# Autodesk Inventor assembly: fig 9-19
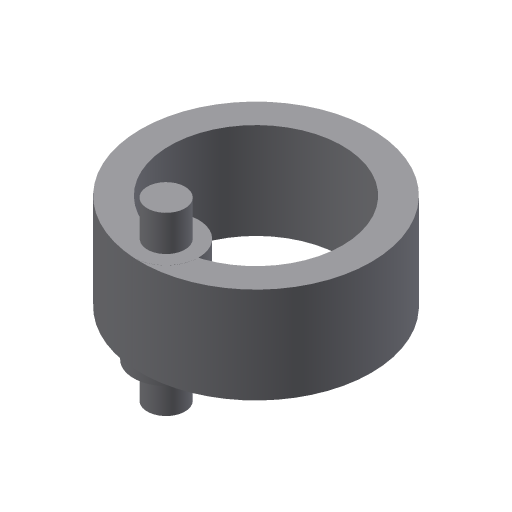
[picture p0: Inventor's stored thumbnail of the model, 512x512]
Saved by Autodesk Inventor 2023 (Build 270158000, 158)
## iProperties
Created: 2002-01
Part Number: fig 9-19
Document SubType Name: Assembly
Designer: ***
Control State: 0
Master: False
Checked Out: False
Shininess: 64.0
Length Units: 11269
Angle Units: 11279
Time Units: 11290
Mass Units: 11283
Length Display Precision: 3
Angle Display Precision: 2
Density: 0.0
Volumn: 0.0
Area: 0.0
PropertySet Name: Model Information
Author: ***
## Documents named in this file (3)
- D:\PROJECTS\Project 2022\Autodesk Inventor For Professional 2023\RESOURCES INVENTOR 2023\RESOURCES INVENTOR 2023\Inventor_2023_Part\Inventor_2023_Part\c09_Inv_2023_prt\fig 9-19.iam
- D:\PROJECTS\Project 2022\Autodesk Inventor For Professional 2023\RESOURCES INVENTOR 2023\RESOURCES INVENTOR 2023\Inventor_2023_Part\Inventor_2023_Part\c09_Inv_2023_prt\Part8.ipt
- D:\PROJECTS\Project 2022\Autodesk Inventor For Professional 2023\RESOURCES INVENTOR 2023\RESOURCES INVENTOR 2023\Inventor_2023_Part\Inventor_2023_Part\c09_Inv_2023_prt\Part9.ipt
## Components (2 placed, 2 different names)
1. Part8:1 — Flush:1
2. Part9:1 — Flush:1
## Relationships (1: Flush 1)
- Flush:1: Part8:1 ↔ Part9:1
